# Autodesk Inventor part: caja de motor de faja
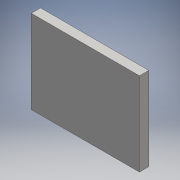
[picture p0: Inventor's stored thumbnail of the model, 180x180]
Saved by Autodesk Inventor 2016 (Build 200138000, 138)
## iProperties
Created: 2016-06
Part Number: caja de motor de faja
Material: Genérico
Document SubType Name: Modeling
Designer: adm
Density: 1 g/cm^3
Appearance: Valor por defecto
Author: adm
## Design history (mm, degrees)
sketch "Boceto1"
  geometry: L1 (-17.5, -1.5)-(17.5, -1.5); L2 (17.5, -1.5)-(17.5, 1.5); L3 (17.5, 1.5)-(-17.5, 1.5); L4 (-17.5, 1.5)-(-17.5, -1.5); L5 (-17.5, -1.5)-(17.5, 1.5); L6 (17.5, -1.5)-(-17.5, 1.5); 1 further point
  constraints: 12 end point, 2 midpoint, 2 parallel, 1 horizontal, 1 perpendicular
  dimensions: "d0" = 35 distance of L3.end L2.end; "d1" = 3 distance of L2.end L1.end
extrude "Extrusión1" new body sketch "Boceto1" distance "d2" = 27; taper "d3" = 0 deg
sketch "Boceto2"
  geometry: 1 further point
node "Sólido1"
